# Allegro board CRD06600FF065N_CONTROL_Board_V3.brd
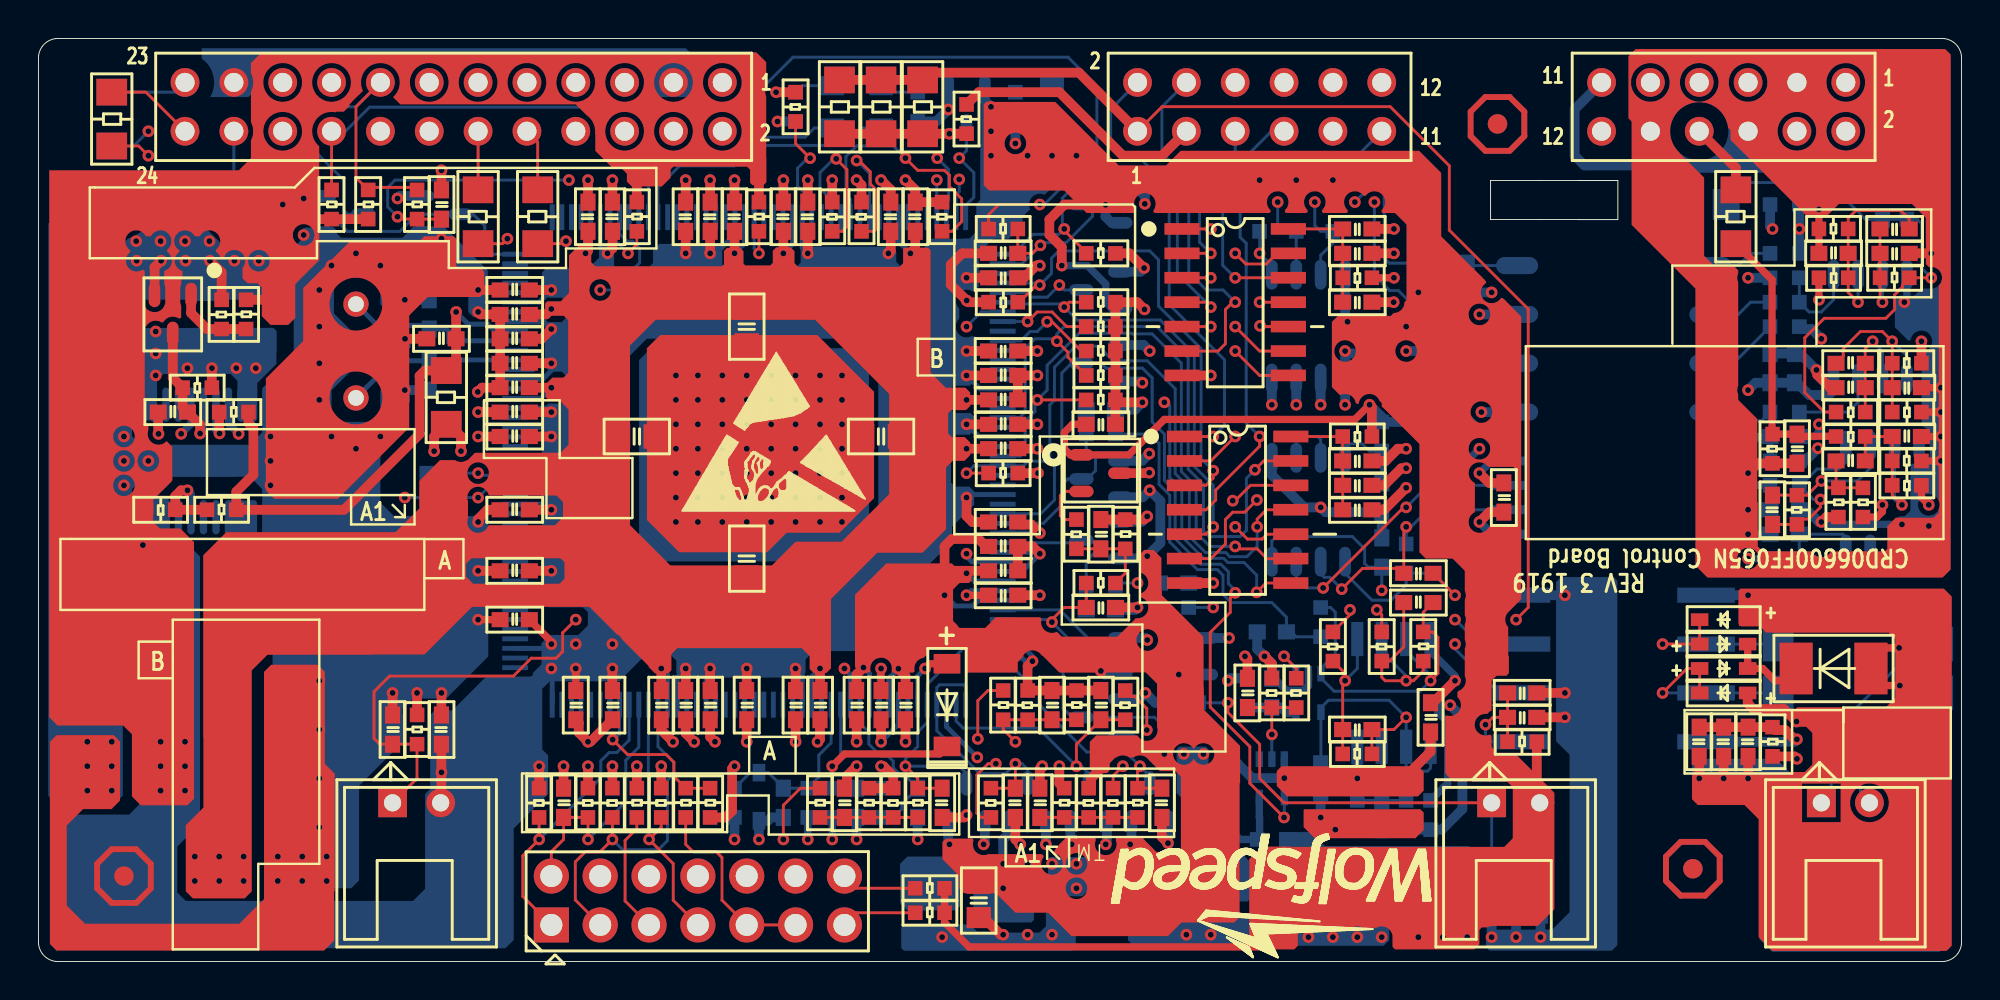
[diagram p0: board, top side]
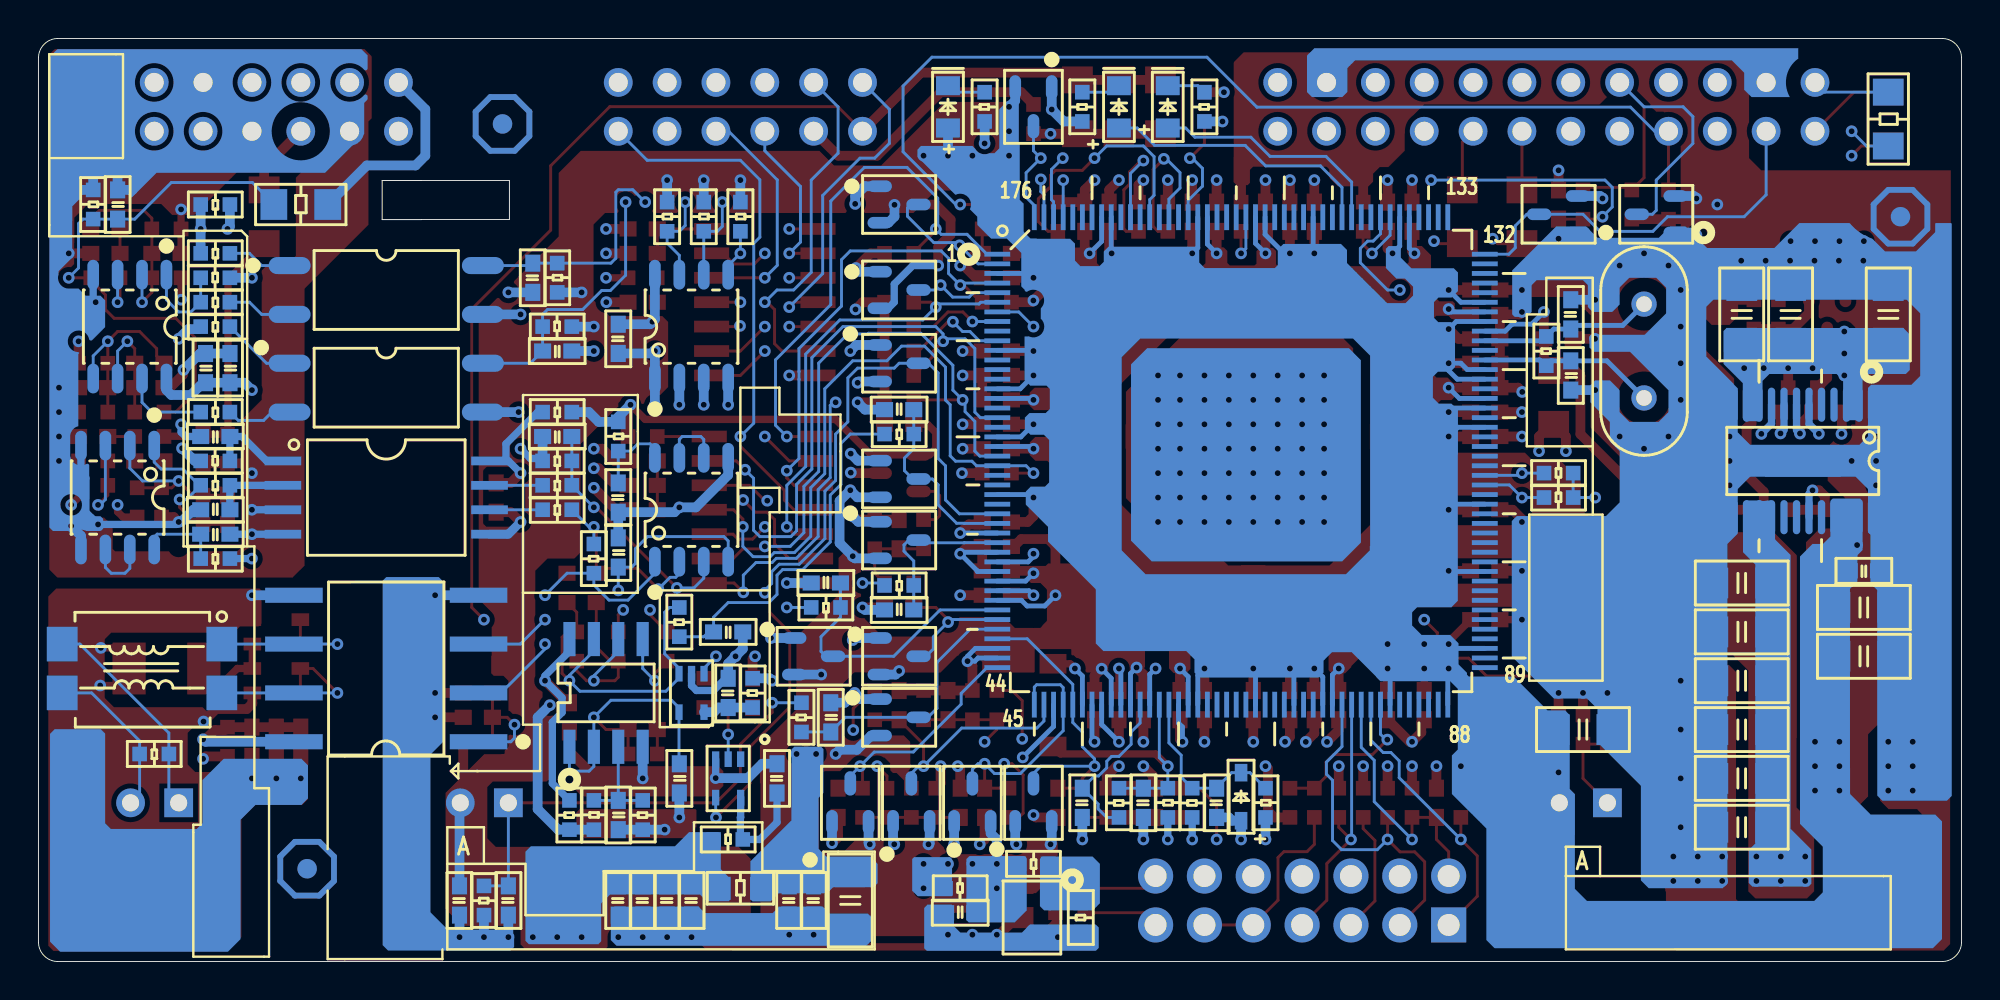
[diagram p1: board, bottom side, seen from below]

Outline 100 x 48.01 mm; copper layers: TOP, ART02, ART03, BOTTOM. Coordinates in mm from the lower left corner of the outline.
Outline path: 0,46.99 arc(0.3,47.71) 1.02,48.01 98.98,48.01 arc(99.7,47.71) 100,46.99 100,1.02 arc(99.7,0.3) 98.98,0 1.02,0 arc(0.3,0.3) 0,1.02 0,46.99 ; 75.51,40.62 80.08,40.62 80.08,40.62 82.13,40.62 82.13,38.59 80.08,38.59 80.08,38.59 75.51,38.59 75.51,40.62

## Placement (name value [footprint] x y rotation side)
C237  22n  [C0603]  91.44 26.67 90 top
C254  0.022n  [C0603]  20.32 30.48 90 bottom
C262  330p  [C0603]  68.58 12.06 0 top
C263  0.1u  [C0603]  64.14 13.97 270 bottom
C264  1n  [C0603]  62.87 13.97 90 top
C265  0.1u  [C0603]  61.59 9.53 270 bottom
C266  0.1u  [C0603]  72.39 12.7 90 top
C267  0.47u  [C0603]  69.85 7.62 90 bottom
C268  0.47u  [C0603]  66.67 9.53 90 bottom
C371  0.022n  [C0603]  20.32 33.66 270 bottom
C378  0.1u  [C0603]  27.3 8.26 90 top
C392  0.12n  [C0603]  50.16 36.83 180 top
C393  2.2n  [C0603]  50.8 8.26 270 top
C394  3.3n  [C0603]  58.42 8.26 270 top
C395  DNP  [C0603]  52.07 8.26 90 top
C396  0.1u  [C0603]  69.85 32.38 270 bottom
C397  680p  [C0603]  52.07 2.54 0 bottom
C398  0.1u  [C0603]  69.85 3.17 270 bottom
C399  0.1u  [C0603]  68.58 3.17 270 bottom
C400  0.1u  [C0603]  67.31 3.17 270 bottom
C401  0.1u  [C0603]  66.04 3.17 270 bottom
C402  0.1u  [C0603]  60.96 3.17 270 bottom
C403  0.1u  [C0603]  59.69 3.17 270 bottom
C404  4.7u  [C1206]  57.78 3.17 270 bottom
C405  1u  [C0603]  78.11 3.17 270 bottom
C406  1u  [C0603]  20.95 12.06 270 top
C407  0.47u  [C0603]  75.56 3.17 270 bottom
C408  0.47u  [C0603]  58.8 12.7 90 bottom
C409  0.47u  [C0603]  18.41 12.06 90 top
C410  0.47u  [C0603]  59.05 19.68 0 bottom
C445  0.1u  [C0603]  90.81 27.3 180 bottom
C446  2.2n  [C0603]  90.81 23.5 0 bottom
C447  0.1u  [C0603]  76.2 24.13 90 top
C448  0.33n  [C0603]  73.03 27.3 180 bottom
C449  0.33n  [C0603]  71.75 20.19 0 top
C450  0.47u  [C0603]  69.85 21.27 90 bottom
C451  0.47u  [C0603]  69.85 24.13 270 bottom
C452  4.7n  [C0603]  55.24 13.34 90 top
C453  0.15n  [C0603]  97.16 27.3 180 top
C454  0.15n  [C0603]  94.23 26.04 180 top
C455  0.15n  [C0603]  90.17 23.5 270 top
C457  0.47u  [C0603]  90.81 22.23 180 bottom
C458  0.47n  [C0603]  96.52 36.83 0 top
C459  0.1u  [C0603]  93.34 36.83 180 top
C460  0.15n  [C0603]  96.52 38.1 0 top
C462  0.47u  [C0603]  90.04 30.86 90 bottom
C463  0.12n  [C0603]  74.3 35.56 270 bottom
C464  0.12n  [C0603]  73.03 31.75 180 bottom
C465  0.47n  [C0603]  94.23 29.84 180 top
C466  0.15n  [C0603]  94.23 31.11 180 top
C467  0.12n  [C0603]  97.16 29.84 0 top
C471  1u  [C0603]  77.15 13.97 0 top
C472  0.1u  [C0603]  77.15 12.7 0 top
C473  1u  [C0603]  86.36 11.43 270 top
C474  0.1u  [C0603]  88.9 11.43 270 top
C475  0.01u  [C0603]  87.63 11.43 270 top
C483  2.2n  [C0603]  64.14 17.14 180 bottom
C484  4.7n  [C0603]  55.24 28.7 0 bottom
C488  2.2n  [C0603]  52.7 13.34 90 top
C489  4.7n  [C0603]  55.24 18.29 0 bottom
C490  1n  [C0603]  41.91 8.26 90 top
C491  3.3n  [C0603]  46.99 8.26 270 top
C492  0.01u  [C0603]  55.24 22.23 90 top
C493  0.01u  [C0603]  55.24 18.41 0 top
C494  0.1u  [C0603]  55.24 27.94 0 top
C495  330p  [C0603]  71.75 18.67 180 top
C496  10u  [C1206]  11.43 33.66 90 bottom
C497  10u  [C1206]  8.89 33.66 90 bottom
C499  0.1u  [C0603]  5.08 20.32 180 bottom
C500  10u  [C1206]  5.08 18.41 180 bottom
C501  10u  [C1206]  5.08 15.88 180 bottom
C504  10u  [C1206]  3.81 33.66 90 bottom
C505  0.1u  [C0603]  6.99 28.57 180 top
C506  10u  [C1206]  19.68 12.06 180 bottom
C507  10u  [C1206]  11.43 14.61 0 bottom
C508  10u  [C1206]  11.43 12.06 0 bottom
C509  10u  [C1206]  11.43 17.14 0 bottom
C510  10u  [C1206]  11.43 9.53 0 bottom
C511  10u  [C1206]  11.43 6.99 0 bottom
C512  2.2u  [C0805]  36.83 33.02 270 top
C513  2.2u  [C0805]  43.81 27.3 180 top
C514  2.2u  [C0805]  36.83 20.95 90 top
C515  2.2u  [C0805]  31.11 27.3 0 top
C516  10u  [C1206]  11.43 19.68 0 bottom
C518  0.1u  [C0603]  38.73 8.26 270 bottom
C519  22n  [C0603]  20.95 32.38 180 top
C520  0.1u  [C0603]  50.16 35.56 0 top
C521  2.2u  [C0603]  50.16 19.05 0 top
C522  2.2u  [C0603]  45.59 38.73 270 top
C523  2.2u  [C0603]  44.32 38.73 270 top
C524  2.2u  [C0603]  40.01 38.73 270 top
C525  2.2u  [C0603]  38.73 38.73 270 top
C526  2.2u  [C0603]  36.2 38.73 270 top
C527  2.2u  [C0603]  34.92 38.73 270 top
C528  2.2u  [C0603]  33.66 38.73 270 top
C529  2.2u  [C0603]  29.84 38.73 270 top
C530  2.2u  [C0603]  28.57 38.73 270 top
C531  2.2u  [C0603]  24.77 34.92 180 top
C532  2.2u  [C0603]  24.77 33.66 180 top
C533  2.2u  [C0603]  24.77 32.38 180 top
C534  2.2u  [C0603]  24.77 31.11 180 top
C535  2.2u  [C0603]  24.77 29.84 180 top
C536  2.2u  [C0603]  24.77 28.57 180 top
C537  2.2u  [C0603]  24.77 27.3 180 top
C538  2.2u  [C0603]  24.77 23.5 180 top
C539  2.2u  [C0603]  24.77 20.32 180 top
C540  2.2u  [C0603]  24.77 17.78 180 top
C541  2.2u  [C0603]  27.94 13.34 90 top
C542  2.2u  [C0603]  29.84 13.34 90 top
C543  2.2u  [C0603]  32.38 13.34 90 top
C544  2.2u  [C0603]  33.66 13.34 90 top
C545  2.2u  [C0603]  34.92 13.34 90 top
C546  2.2u  [C0603]  36.83 13.34 90 top
C547  2.2u  [C0603]  39.37 13.34 90 top
C548  2.2u  [C0603]  40.64 13.34 90 top
C549  2.2u  [C0603]  45.09 13.34 90 top
C550  2.2u  [C0603]  43.81 13.34 90 top
C551  2.2u  [C0603]  42.55 13.34 90 top
C552  0.1u  [C0603]  50.16 31.75 0 top
C553  0.1u  [C0603]  50.16 30.48 180 top
C554  2.2u  [C0603]  50.16 29.21 180 top
C555  0.1u  [C0603]  50.16 27.94 180 top
C556  2.2u  [C0603]  50.16 26.67 180 top
C557  0.1u  [C0603]  50.16 22.86 180 top
C558  2.2u  [C0603]  50.16 21.59 180 top
C559  2.2u  [C0603]  50.16 20.32 180 top
C560  0.1u  [C0603]  68.58 38.1 0 top
C561  0.01u  [C0603]  68.58 34.29 0 top
C562  1u  [C0603]  68.58 36.83 0 top
C563  0.1u  [C0603]  68.58 26.04 0 top
C564  0.01u  [C0603]  68.58 23.5 0 top
C565  1u  [C0603]  68.58 24.77 0 top
C566  0.47u  [C0603]  91.31 30.86 90 bottom
C592  2.2u  [C0805]  48.9 3.17 270 top
C593  1n  [C0603]  42.55 8.26 270 bottom
C594  0.47n  [C0603]  95.89 39.37 90 bottom
C595  1u  [C0603]  45.72 8.26 270 bottom
C596  0.12n  [C0603]  20.95 39.37 90 top
D48  2.2V  [SOD-123]  47.24 13.34 270 top
D84  BAV99  [SOT-23]  59.69 15.88 270 bottom
D85  BAV99  [SOT-23]  55.24 15.88 270 bottom
D86  BAV99  [SOT-23]  55.24 31.11 270 bottom
D87  BAV99  [SOT-23]  57.78 8.26 180 bottom
D88  BAV99  [SOT-23]  55.24 25.1 270 bottom
D89  BAV99  [SOT-23]  54.61 8.26 180 bottom
D90  BAV99  [SOT-23]  51.44 8.26 180 bottom
D91  BAV99  [SOT-23]  48.26 8.26 180 bottom
D92  BAV99  [SOT-23]  55.24 12.7 270 bottom
D93  BAV99  [SOT-23]  55.24 21.92 270 bottom
D94  BAV99  [SOT-23]  55.24 34.92 270 bottom
D95  BAV99  [SOT-23]  55.24 39.37 270 bottom
D96  BAV99  [SOT-23]  15.88 38.86 90 bottom
D97  BAV99  [SOT-23]  20.95 38.86 90 bottom
D98  BAV99  [SOT-23]  48.26 44.45 0 bottom
D102  RC-CL-170R-0805  [LED0805]  41.27 44.45 90 bottom
D103  RC-CL-170R-0805  [LED0805]  43.81 44.45 90 bottom
D104  RC-CL-170R-0805  [LED0805]  52.7 44.45 90 bottom
D110  BAS21WS-TP  [SOD-323]  87.63 13.97 180 top
D111  SMBJ15CA  [SMB]  93.34 15.24 180 top
D112  BAS21WS-TP  [SOD-323]  87.63 15.24 0 top
D113  BAS21WS-TP  [SOD-323]  87.63 17.78 180 top
D114  BAS21WS-TP  [SOD-323]  87.63 16.51 0 top
J2  PIN2*12-2.54-F  [CON_2MM54_12X2]  21.59 44.45 180 top
J3  PIN2*6-2.54-F  [CON_2MM54_6X2]  63.5 44.45 0 top
J4  PIN2*6-2.54-F  [CON_2MM54_6X2]  87.63 44.45 180 top
J5  2*7P 2.54  [CON_2MM54_7X2]  34.29 3.17 180 top
J11  XHB2.54-2P-F  [CON_2MM54_2X1]  92.71 8.26 180 top
J17  1*2P  [CONNECT_2MM54_2X1]  75.56 8.26 180 top
J18  1*2P  [CONNECT_2MM54_2X1]  18.41 8.26 180 top
L21  33uH 0.2A  [R0805]  63.5 3.81 0 bottom
NOREF  -  []  280.71 1.57 0 top
NOREF#2  -  []  38.34 26.64 0 top
NOREF#3  #VAL  [unnamed#2]  86.03 4.83 0 top
NOREF#4  -  []  0.39 -5 90 top
NOREF#5  -  []  0.01 -3.22 0 top
NOREF#6  -  []  0.01 -5.17 0 top
NOREF#7  -  []  187.11 64.82 0 top
NOREF#8  -  []  0.54 0 90 top
NOREF#9  #VAL  [unnamed#2]  75.87 43.56 0 top
NOREF#10  #VAL  [unnamed#2]  4.45 4.45 0 top
NOREF#11  #VAL  [unnamed#2]  3.17 38.73 180 bottom
NOREF#12  #VAL  [unnamed#2]  86.03 4.83 180 bottom
NOREF#13  #VAL  [unnamed#2]  75.87 43.56 180 bottom
Q1  2N7002/SOT  [SOT-23]  6.99 33.66 180 top
R16  1M  [R1206]  25.96 38.73 270 top
R49  470K  [R1206]  3.81 43.81 90 bottom
R58  24K  [R0603]  51.44 13.34 270 top
R133  12K  [R0603]  90.17 26.67 270 top
R221  1M  [R0603]  21.59 31.75 270 bottom
R224  3.9k  [R0603]  68.58 7.62 270 bottom
R225  3.9k  [R0603]  71.12 7.62 90 bottom
R226  13.3k  [R0603]  68.58 10.79 180 top
R229  10K  [R0603]  65.41 13.97 270 top
R230  DNP  [R0603]  64.14 13.97 270 top
R327  1R  [R0603]  31.11 38.73 90 top
R400  1R  [R0603]  37.47 38.73 90 top
R404  10k  [R0603]  26.04 8.26 270 top
R405  10k  [R0603]  29.84 8.26 270 top
R406  10k  [R0603]  32.38 8.26 270 top
R407  10k  [R0603]  34.92 8.26 90 top
R408  0  [R0603]  33.66 8.26 90 top
R409  0  [R0603]  31.11 8.26 90 top
R410  470  [R0603]  28.57 8.26 270 top
R411  2.2k  [R0603]  46.35 3.81 180 top
R412  2.2k  [R0603]  46.35 2.54 180 top
R414  2k  [R0603]  55.24 33.02 180 top
R415  2k  [R0603]  55.24 31.75 180 top
R416  2k  [R0603]  55.24 29.21 180 top
R417  2k  [R0603]  50.16 25.4 180 top
R418  2k  [R0603]  41.27 38.73 270 top
R419  2k  [R0603]  39.37 44.45 270 top
R420  2k  [R0603]  46.99 38.73 270 top
R421  2k  [R0603]  42.8 38.73 270 top
R422  2k  [R0603]  55.24 30.48 180 top
R423  2k  [R0603]  55.24 36.83 180 top
R424  2k  [R0603]  50.16 34.29 0 top
R425  2k  [R0603]  55.24 34.29 180 top
R431  1k  [R0603]  50.16 38.1 180 top
R432  1k  [R0603]  49.53 8.26 270 top
R433  DNP  [R0603]  54.61 8.26 270 top
R434  DNP  [R0603]  53.34 8.26 90 top
R435  0  [R0603]  55.88 8.26 270 top
R436  1k  [R0603]  57.15 8.26 90 top
R437  10k  [R0603]  63.5 38.73 90 bottom
R438  10k  [R0603]  65.41 38.73 90 bottom
R439  10k  [R0603]  67.31 38.73 90 bottom
R440  200  [R0603]  52.07 3.81 0 bottom
R441  1k  [R0603]  48.26 5.08 180 bottom
R442  3.57k  [R0603]  45.8 2.29 270 bottom
R443  2k  [R0603]  39.37 44.45 270 bottom
R444  2k  [R0603]  45.72 44.45 270 bottom
R445  2k  [R0603]  50.8 44.45 270 bottom
R446  2k  [R0603]  76.83 3.17 270 bottom
R447  3.3k  [R0603]  60.33 12.7 270 bottom
R448  2k  [R0603]  19.68 12.06 90 top
R449  3.3k  [R0603]  59.05 18.41 180 bottom
R482  2k  [R0603]  90.81 24.77 180 bottom
R483  10k  [R0603]  73.03 24.77 180 bottom
R484  10k  [R0603]  73.03 26.04 180 bottom
R485  10k  [R0603]  73.03 23.5 180 bottom
R486  10k  [R0603]  71.12 20.95 270 bottom
R487  2k  [R0603]  56.52 13.34 270 top
R488  150k  [R0603]  94.23 27.3 0 top
R489  100k  [R0603]  97.16 26.04 180 top
R491  100k  [R0603]  91.44 23.5 270 top
R492  1M  [R0603]  97.16 24.77 0 top
R493  1M  [R0603]  94.87 23.88 90 top
R494  150k  [R0603]  93.6 23.88 90 top
R495  2k  [R0603]  96.52 35.56 180 top
R496  2k  [R0603]  93.34 35.56 0 top
R497  3k  [R0603]  93.34 38.1 180 top
R499  2k  [R0603]  90.81 34.29 180 bottom
R500  3K  [R0603]  90.81 36.83 180 bottom
R502  3.9k  [R0603]  73.03 35.56 90 bottom
R503  3K  [R0603]  90.81 33.02 180 bottom
R505  3.9k  [R0603]  73.03 33.02 0 bottom
R506  1k  [R0603]  94.23 28.57 0 top
R507  47k  [R0603]  97.16 31.11 180 top
R508  1.1k  [R0603]  97.16 28.57 0 top
R510  1k  [R0603]  90.81 28.57 180 bottom
R514  620  [R0603]  20.95 24.13 0 bottom
R515  10k  [R0603]  20.95 25.4 0 bottom
R516  0  [R0603]  90.17 11.43 90 top
R517  120  [R0603]  93.98 10.79 180 bottom
R524  1k  [R0603]  66.67 17.65 270 bottom
R525  1k  [R0603]  55.24 27.43 180 bottom
R528  24k  [R0603]  53.98 13.34 90 top
R529  1k  [R0603]  55.24 19.56 180 bottom
R530  24k  [R0603]  43.18 8.26 90 top
R531  1k  [R0603]  45.72 8.26 90 top
R532  100  [R0603]  53.98 22.23 270 top
R533  470k  [R0603]  56.52 22.23 90 top
R534  3.3k  [R0603]  55.24 19.68 180 top
R535  13.3k  [R0603]  72.01 16.38 90 top
R536  10k  [R0603]  8.26 29.84 0 top
R537  1.5k  [R0603]  10.79 33.66 90 top
R538  12k  [R0603]  9.53 33.66 270 top
R540  100k  [R0603]  6.35 23.5 0 top
R541  0R  [R0603]  9.53 23.5 180 top
R544  2.2k  [R0603]  40.01 8.26 270 bottom
R545  2.2k  [R0603]  36.2 8.26 90 bottom
R546  10k  [R1206]  21.21 29.34 270 top
R547  0  [R0603]  10.16 28.57 180 top
R549  2.2R  [R0603]  68.58 35.56 0 top
R550  2.2R  [R0603]  68.58 27.3 0 top
R569  10k  [R0603]  90.81 35.56 0 bottom
R572  1M  [R1206]  22.86 38.73 270 top
R573  620k  [R1206]  88.27 38.73 270 top
R574  620k  [R1206]  86.36 39.37 0 bottom
R575  12K  [R0603]  97.16 39.37 90 bottom
R578  24K  [R0603]  44.45 8.26 270 top
R579  470K  [R1206]  3.81 43.81 90 top
R580  20R  [R1206]  45.97 44.45 90 top
R581  20R  [R1206]  43.81 44.45 90 top
R582  20R  [R1206]  41.66 44.45 90 top
R583  1k  [R0603]  41.27 8.26 90 bottom
R588  0  [R0603]  48.26 43.81 270 top
R589  10R  [R0603]  72.39 7.62 270 bottom
R590  10R  [R0603]  62.87 13.97 270 bottom
R591  10R  [R0603]  64.14 6.35 0 bottom
R592  10R  [R0603]  90.81 20.95 180 bottom
R593  10R  [R0603]  90.81 26.04 0 bottom
R594  10R  [R0603]  73.03 28.57 180 bottom
R595  10R  [R0603]  69.85 27.3 90 bottom
R597  10R  [R0603]  90.81 39.37 180 bottom
R598  10R  [R0603]  77.15 11.43 180 top
R599  10k  [R0603]  43.81 8.26 270 bottom
R600  10K  [R0603]  50.16 13.34 90 top
R601  10K  [R0603]  40.64 8.26 90 top
R602  10k  [R0603]  69.85 16.38 270 top
R603  10k  [R0603]  67.31 16.38 270 top
R604  10k  [R0603]  15.24 39.37 90 top
R605  1k  [R0603]  19.68 39.37 90 top
R606  10k  [R0603]  17.14 39.37 90 top
T1  TRNSFMR TV105  [ZJYS81]  94.61 15.24 0 bottom
U9  AZ431  [SOT23_1-32]  48.34 2.29 0 bottom
U28  TMS320F28377D  [LQFP176-050-2424]  37.47 26.04 270 bottom
U32  24C16BT-I/SN  [SOIC-8]  66.04 33.02 90 bottom
U36  SN74LVC1G17  [DCK]  64.14 9.53 0 bottom
U37  TLV3201  [SOT23-5]  66.04 13.97 0 bottom
U43  ACPL-C870-500E  [SSO-8]  81.92 24.13 270 bottom
U44  OPA2376  [SOIC-8]  95.89 24.13 270 bottom
U45  OPA2376  [SOIC-8]  66.04 23.5 90 bottom
U48  LM2903  [SOIC-8]  95.25 33.02 270 bottom
U53  1050  [SO-G8]  81.92 15.24 0 bottom
U55  LM50CIM3  [SOT-23]  55.24 25.4 270 top
U56  OPA2376AIDR  [WCSP-8]  70.48 13.97 90 bottom
U57  TPS70445PWP_TSSOP24  [TSSOP24]  8.26 26.04 270 bottom
U58  MC74VHCT50A_SOIC14  [SOIC14]  62.23 34.29 0 top
U59  MC74VHCT50A_SOIC14  [SOIC14]  62.35 23.5 0 top
U60  -  [TCLT1003]  81.92 34.92 180 bottom
U61  -  [TCLT1003]  81.92 29.84 180 bottom
Y1  HLX32 20MHz  [TSX-3225]  16.51 31.75 270 bottom
ZD3  2.5V  [SOD-323]  37.47 8.57 90 bottom

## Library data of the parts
C237 C254 C262-C268 C371 C378 C392-C403 C405-C410 C445-C455 C457-C460 C462-C467 C471-C475 C483 C484 C488-C495 C499 C505 C518-C566 C593-C596 = C0603: Tolerance: #TOL; User Part Number: HAMP
C404 C496 C497 C500 C501 C504 C506-C511 C516 = C1206: Tolerance: #TOL; User Part Number: HAMP
C512-C515 C592 = C0805: Tolerance: #TOL; User Part Number: HAMP
D48 = SOD-123: User Part Number: HAMP; Tolerance: #TOL
D84-D98 Q1 U55 = SOT-23: Tolerance: #TOL; User Part Number: HAMP
D102-D104 = LED0805: Tolerance: #TOL; User Part Number: HAMP
D110 D112-D114 ZD3 = SOD-323: Tolerance: #TOL; User Part Number: HAMP
D111 = SMB: Tolerance: #TOL; User Part Number: HAMP
J2 = CON_2MM54_12X2: Tolerance: #TOL; User Part Number: HAMP
J3 J4 = CON_2MM54_6X2: Tolerance: #TOL; User Part Number: HAMP
J5 = CON_2MM54_7X2: Tolerance: #TOL; User Part Number: HAMP
J11 = CON_2MM54_2X1: Tolerance: #TOL; User Part Number: HAMP
J17 J18 = CONNECT_2MM54_2X1: Tolerance: #TOL; User Part Number: HAMP
L21 = R0805: Tolerance: #TOL; User Part Number: HAMP
NOREF#3 NOREF#9-NOREF#13 = -: Tolerance: #TOL; User Part Number: HAMP
R16 R49 R546 R572-R574 R579-R582 = R1206: Tolerance: #TOL; User Part Number: HAMP
R58 R133 R221 R224-R226 R229 R230 R327 R400 R404-R412 R414-R425 R431-R449 R482-R489 R491-R497 R499 R500 R502 R503 R505-R508 R510 R514-R517 R524 R525 R528-R538 R540 R541 R544 R545 R547 R549 R550 R569 R575 R578 R583 R588-R595 R597-R606 = R0603: Tolerance: #TOL; User Part Number: HAMP
T1 = ZJYS81: Tolerance: #TOL; User Part Number: HAMP
U9 = SOT23_1-32: Tolerance: #TOL; User Part Number: HAMP
U28 = LQFP176-050-2424: Tolerance: #TOL; User Part Number: HAMP
U32 U44 U45 U48 = SOIC-8: Tolerance: #TOL; User Part Number: HAMP
U36 = DCK: Tolerance: #TOL; User Part Number: HAMP
U37 = SOT23-5: Tolerance: #TOL; User Part Number: HAMP
U43 = SSO-8: Tolerance: #TOL; User Part Number: HAMP
U53 = SO-G8: Tolerance: #TOL; User Part Number: HAMP
U56 = WCSP-8: Tolerance: #TOL; User Part Number: HAMP
U57 = TSSOP24: Tolerance: #TOL; User Part Number: HAMP
U58 U59 = SOIC14: Tolerance: #TOL; User Part Number: HAMP
U60 U61 = TCLT1003: Tolerance: #TOL; User Part Number: HAMP
Y1 = TSX-3225: Tolerance: #TOL; User Part Number: HAMP

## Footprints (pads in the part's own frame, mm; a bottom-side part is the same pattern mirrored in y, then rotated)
C0603
  rect 0.889x0.787 smd: 1(-0.76,0) 2(0.76,0)
C0805
  rect 1.092x1.27 smd: 1(-0.89,0) 2(0.89,0)
C1206
  rect 1.397x1.6 smd: 1(-1.4,0) 2(1.4,0)
CON_2MM54_2X1
  rect 1.499x1.499 hole 0.889: 1(0,0)
  round 1.499 hole 0.889: 2(-2.5,0)
CON_2MM54_6X2
  round 1.499 hole 0.991: 1(-6.35,-1.27) 2(-6.35,1.27) 3(-3.81,-1.27) 4(-3.81,1.27) 5(-1.27,-1.27) 6(-1.27,1.27) 7(1.27,-1.27) 8(1.27,1.27) 9(3.81,-1.27) 10(3.81,1.27) 11(6.35,-1.27) 12(6.35,1.27)
CON_2MM54_7X2
  rect 1.829x1.829 hole 1.143: 1(7.62,1.271)
  round 1.829 hole 1.143: 2(7.62,-1.271) 3(5.08,1.271) 4(5.08,-1.271) 5(2.54,1.271) 6(2.54,-1.271) 7(0,1.271) 8(0,-1.271) 9(-2.54,1.271) 10(-2.54,-1.271) 11(-5.08,1.271) 12(-5.08,-1.271) 13(-7.62,1.271) 14(-7.62,-1.271)
CON_2MM54_12X2
  round 1.499 hole 0.991: 1(-13.97,-1.27) 2(-13.97,1.27) 3(-11.43,-1.27) 4(-11.43,1.27) 5(-8.89,-1.27) 6(-8.89,1.27) 7(-6.35,-1.27) 8(-6.35,1.27) 9(-3.81,-1.27) 10(-3.81,1.27) 11(-1.27,-1.27) 12(-1.27,1.27) 13(1.27,-1.27) 14(1.27,1.27) 15(3.81,-1.27) 16(3.81,1.27) 17(6.35,-1.27) 18(6.35,1.27) 19(8.89,-1.27) 20(8.89,1.27) 21(11.43,-1.27) 22(11.43,1.27) 23(13.97,-1.27) 24(13.97,1.27)
CONNECT_2MM54_2X1
  rect 1.499x1.499 hole 0.889: 1(0,0)
  round 1.499 hole 0.889: 2(-2.5,0)
DCK
  rect 0.381x0.813 smd: 1(-0.65,-1) 2(0,-1) 3(0.65,-1) 4(0.65,1) 5(-0.65,1)
LED0805
  rect 0.991x1.245 smd: 1(1.1,0) 2(-1.1,0)
LQFP176-050-2424
  rect 8.636x8.636 smd: 0(0,0)
  rect 0.254x1.346 smd: 1(-10.75,-12.675) 2(-10.25,-12.675) 3(-9.75,-12.675) 4(-9.25,-12.675) 5(-8.75,-12.675) 6(-8.25,-12.675) 7(-7.75,-12.675) 8(-7.25,-12.675) 9(-6.75,-12.675) 10(-6.25,-12.675) 11(-5.75,-12.675) 12(-5.25,-12.675) 13(-4.75,-12.675) 14(-4.25,-12.675) 15(-3.75,-12.675) 16(-3.25,-12.675) 17(-2.75,-12.675) 18(-2.25,-12.675) 19(-1.75,-12.675) 20(-1.25,-12.675) 21(-0.75,-12.675) 22(-0.25,-12.675) 23(0.25,-12.675) 24(0.75,-12.675) 25(1.25,-12.675) 26(1.75,-12.675) 27(2.25,-12.675) 28(2.75,-12.675) 29(3.25,-12.675) 30(3.75,-12.675) 31(4.25,-12.675) 32(4.75,-12.675) 33(5.25,-12.675) 34(5.75,-12.675) 35(6.25,-12.675) 36(6.75,-12.675) 37(7.25,-12.675) 38(7.75,-12.675) 39(8.25,-12.675) 40(8.75,-12.675) 41(9.25,-12.675) 42(9.75,-12.675) 43(10.25,-12.675) 44(10.75,-12.675) 89(10.75,12.675) 90(10.25,12.675) 91(9.75,12.675) 92(9.25,12.675) 93(8.75,12.675) 94(8.25,12.675) 95(7.75,12.675) 96(7.25,12.675) 97(6.75,12.675) 98(6.25,12.675) 99(5.75,12.675) 100(5.25,12.675) 101(4.75,12.675) 102(4.25,12.675) 103(3.75,12.675) 104(3.25,12.675) 105(2.75,12.675) 106(2.25,12.675) 107(1.75,12.675) 108(1.25,12.675) 109(0.75,12.675) 110(0.25,12.675) 111(-0.25,12.675) 112(-0.75,12.675) 113(-1.25,12.675) 114(-1.75,12.675) 115(-2.25,12.675) 116(-2.75,12.675) 117(-3.25,12.675) 118(-3.75,12.675) 119(-4.25,12.675) 120(-4.75,12.675) 121(-5.25,12.675) 122(-5.75,12.675) 123(-6.25,12.675) 124(-6.75,12.675) 125(-7.25,12.675) 126(-7.75,12.675) 127(-8.25,12.675) 128(-8.75,12.675) 129(-9.25,12.675) 130(-9.75,12.675) 131(-10.25,12.675) 132(-10.75,12.675)
  rect 1.346x0.254 smd: 45(12.675,-10.75) 46(12.675,-10.25) 47(12.675,-9.75) 48(12.675,-9.25) 49(12.675,-8.75) 50(12.675,-8.25) 51(12.675,-7.75) 52(12.675,-7.25) 53(12.675,-6.75) 54(12.675,-6.25) 55(12.675,-5.75) 56(12.675,-5.25) 57(12.675,-4.75) 58(12.675,-4.25) 59(12.675,-3.75) 60(12.675,-3.25) 61(12.675,-2.75) 62(12.675,-2.25) 63(12.675,-1.75) 64(12.675,-1.25) 65(12.675,-0.75) 66(12.675,-0.25) 67(12.675,0.25) 68(12.675,0.75) 69(12.675,1.25) 70(12.675,1.75) 71(12.675,2.25) 72(12.675,2.75) 73(12.675,3.25) 74(12.675,3.75) 75(12.675,4.25) 76(12.675,4.75) 77(12.675,5.25) 78(12.675,5.75) 79(12.675,6.25) 80(12.675,6.75) 81(12.675,7.25) 82(12.675,7.75) 83(12.675,8.25) 84(12.675,8.75) 85(12.675,9.25) 86(12.675,9.75) 87(12.675,10.25) 88(12.675,10.75) 133(-12.675,10.75) 134(-12.675,10.25) 135(-12.675,9.75) 136(-12.675,9.25) 137(-12.675,8.75) 138(-12.675,8.25) 139(-12.675,7.75) 140(-12.675,7.25) 141(-12.675,6.75) 142(-12.675,6.25) 143(-12.675,5.75) 144(-12.675,5.25) 145(-12.675,4.75) 146(-12.675,4.25) 147(-12.675,3.75) 148(-12.675,3.25) 149(-12.675,2.75) 150(-12.675,2.25) 151(-12.675,1.75) 152(-12.675,1.25) 153(-12.675,0.75) 154(-12.675,0.25) 155(-12.675,-0.25) 156(-12.675,-0.75) 157(-12.675,-1.25) 158(-12.675,-1.75) 159(-12.675,-2.25) 160(-12.675,-2.75) 161(-12.675,-3.25) 162(-12.675,-3.75) 163(-12.675,-4.25) 164(-12.675,-4.75) 165(-12.675,-5.25) 166(-12.675,-5.75) 167(-12.675,-6.25) 168(-12.675,-6.75) 169(-12.675,-7.25) 170(-12.675,-7.75) 171(-12.675,-8.25) 172(-12.675,-8.75) 173(-12.675,-9.25) 174(-12.675,-9.75) 175(-12.675,-10.25) 176(-12.675,-10.75)
R0603
  rect 0.762x0.762 smd: 1(-0.76,0) 2(0.76,0)
R0805
  rect 0.991x1.194 smd: 1(-1,0) 2(1,0)
R1206
  rect 1.397x1.6 smd: 1(-1.4,0) 2(1.4,0)
SMB
  rect 1.727x2.692 smd: 1(-1.943,0) 2(1.943,0)
SO-G8
  rect 2.997x0.787 smd: 1(-4.8,3.81) 2(-4.8,1.27) 3(-4.8,-1.27) 4(-4.8,-3.81) 5(4.8,-3.81) 6(4.8,-1.27) 7(4.8,1.27) 8(4.8,3.81)
SOD-123
  rect 1.02x1.4 smd: 1(-2.15,0) 2(2.15,0)
SOD-323
  rect 0.914x0.66 smd: 1(-1.25,0) 2(1.25,0)
SOIC14
  rect 1.829x0.61 smd: 1(-2.765,3.81) 2(-2.765,2.54) 3(-2.765,1.27) 4(-2.765,0) 5(-2.765,-1.27) 6(-2.765,-2.54) 7(-2.765,-3.81) 8(2.765,-3.81) 9(2.765,-2.54) 10(2.765,-1.27) 11(2.765,0) 12(2.765,1.27) 13(2.765,2.54) 14(2.765,3.81)
SOIC-8
  oval 1.549x0.61 smd: 1(-2.7,1.905) 2(-2.7,0.635) 3(-2.7,-0.635) 4(-2.7,-1.905) 5(2.7,-1.905) 6(2.7,-0.635) 7(2.7,0.635) 8(2.7,1.905)
SOT23-5
  rect 0.381x0.813 smd: 1(-0.65,-1) 2(0,-1) 3(0.65,-1) 4(0.65,1) 5(-0.65,1)
SOT23_1-32
  oval 0.61x1.27 smd: 1(-0.95,-1.01) 2(0.95,-1.01) 3(0,1.01)
SOT-23
  oval 0.61x1.27 smd: 1(-0.95,-1.01) 2(0.95,-1.01) 3(0,1.01)
SSO-8
  rect 0.457x1.905 smd: 1(-1.905,-5.373) 2(-0.635,-5.373) 3(0.635,-5.373) 4(1.905,-5.373) 5(1.905,5.373) 6(0.635,5.373) 7(-0.635,5.373) 8(-1.905,5.373)
TCLT1003
  oval 2.184x0.889 smd: 1(-5.025,1.27) 2(-5.025,-1.27) 3(5.025,-1.27) 4(5.025,1.27)
TSSOP24
  oval 1.778x0.381 smd: 1(-2.925,3.575) 2(-2.925,2.925) 3(-2.925,2.275) 4(-2.925,1.625) 5(-2.925,0.975) 6(-2.925,0.325) 7(-2.925,-0.325) 8(-2.925,-0.975) 9(-2.925,-1.625) 10(-2.925,-2.275) 11(-2.925,-2.925) 12(-2.925,-3.575) 13(2.925,-3.575) 14(2.925,-2.925) 15(2.925,-2.275) 16(2.925,-1.625) 17(2.925,-0.975) 18(2.925,-0.325) 19(2.925,0.325) 20(2.925,0.975) 21(2.925,1.625) 22(2.925,2.275) 23(2.925,2.925) 24(2.925,3.575)
  rect 1.651x3.937 smd: 25(0,0)
TSX-3225
  round 1.321 hole 0.813: 1(-2.44,0) 2(2.44,0)
unnamed#2
  round 1.016 smd: 1(0,0)
WCSP-8
  rect 1.778x0.635 smd: 1(-2.8,1.905) 2(-2.8,0.635) 3(-2.8,-0.635) 4(-2.8,-1.905) 5(2.8,-1.905) 6(2.8,-0.635) 7(2.8,0.635) 8(2.8,1.905)
ZJYS81
  rect 1.6x1.803 smd: 1(-4.15,-1.27) 2(-4.15,1.27) 3(4.15,1.27) 4(4.15,-1.27)

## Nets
AGND: C254.1 C263.1 C264.2 C265.1 C266.1 C267.1 C268.1 C371.1 C378.2 C392.2 C393.2 C394.2 C395.2 C396.2 C397.2 C398.2 C399.2 C400.2 C401.2 C402.2 C403.2 C404.2 C405.2 C406.1 C407.2 C408.2 C409.2 C410.2 C447.1 C448.1 C450.2 C451.2 C452.2 C463.2 C464.2 C471.2 C472.2 C483.2 C484.2 C488.2 C489.2 C490.2 C491.2 C492.2 C493.2 C494.2 C496.2 C497.2 C499.2 C500.2 C501.2 C504.2 C505.2 C506.2 C507.2 C508.2 C509.2 C510.2 C511.2 C512.2 C513.2 C514.2 C515.2 C516.2 C518.2 C519.2 C520.2 C521.2 C522.1 C523.1 C524.1 C525.1 C526.1 C527.1 C528.1 C529.1 C530.1 C531.2 C532.2 C533.2 C534.2 C535.2 C536.2 C537.2 C538.2 C539.2 C540.2 C541.1 C542.1 C543.1 C544.1 C545.1 C546.1 C547.1 C548.1 C549.1 C550.1 C551.1 C552.2 C553.1 C554.1 C555.1 C556.1 C557.1 C558.1 C559.1 C560.2 C561.2 C562.2 C563.2 C564.2 C565.2 C592.2 C593.2 C595.2 C596.2 D48.1 D84.1 D85.1 D86.1 D87.1 D88.1 D89.1 D90.1 D91.1 D92.1 D93.1 D94.1 D95.1 D96.1 D97.1 D98.1 J2.2 J2.3 J2.4 J2.21 J3.6 J3.8 J5.4 J5.6 J5.8 J5.10 J5.12 Q1.2 R58.1 R224.2 R230.1 R410.1 R414.1 R415.1 R416.1 R417.1 R418.1 R419.1 R420.1 R421.1 R422.1 R423.1 R424.1 R425.1 R434.2 R442.2 R443.2 R444.2 R445.2 R446.2 R448.2 R484.1 R528.2 R530.2 R533.2 R538.1 R545.1 R578.1 R580.1 R581.1 R582.1 R588.2 U9.3 U28.0 U28.30 U28.32 U28.33 U28.34 U28.42 U28.43 U28.47 U28.50 U28.51 U28.52 U28.57 U28.60 U32.1 U32.2 U32.3 U32.4 U36.3 U37.2 U43.5 U45.5 U53.4 U55.3 U56.4 U57.1 U57.6 U57.9 U57.12 U57.13 U57.24 U57.25 U58.7 U59.7 U60.3 U61.3 ZD3.1
DGND: C237.1 C445.1 C446.2 C453.1 C457.2 C458.2 C459.2 C462.2 C465.2 C467.2 C566.2 C594.2 J4.3 J4.6 J4.10 R133.2 R489.1 R494.1 R497.2 R508.2 R575.2 U43.3 U43.4 U44.4 U44.5 U48.4
VDD: C507.1 C508.1 C509.1 C510.1 C511.1 C512.1 C513.1 C514.1 C515.1 C516.1 C522.2 C525.2 C526.2 C530.2 C532.1 C535.1 C543.2 C548.2 C554.2 C556.2 U28.16 U28.21 U28.61 U28.76 U28.117 U28.126 U28.137 U28.153 U28.158 U28.169 U57.14 U57.15 U57.16
/TRST_P: C378.1 J5.2 R410.2 U28.79
/WP_PFC: R439.1 U28.175 U32.7
_AD_DC_CUR: C393.1 D90.3 R432.1 U28.45 U28.48
_AD_DCTEMP: C408.1 D92.3 R447.2 U28.40
_AD_PFCTEMP: C410.1 D84.3 R449.2 U28.38
_AD_VAC: C484.1 D88.3 R525.2 U28.29
_AD_VPFC_CTRL: C489.1 D93.3 R529.2 U28.31
_AD_VPFC_PROTECT: C491.1 D91.3 R531.2 U28.41 U28.49
_DCOCP: C392.1 D95.3 R431.1 U28.2
_PFC_OCP: C596.1 R605.1 U28.7
_PFCCURBSAMP: C394.1 D87.3 R436.2 U28.44
AC_L_SAMP_D: J2.10 R16.1
AC_N_D: J2.12 R572.1
AD_AIR_TEMP: C493.1 D85.3 R534.2 U28.39
AD_DC_CUR: J2.16 R432.2
AD_DCVOLT1: C452.1 D89.3 R487.2 U28.46
CAN5V_GND: C473.2 C474.2 C475.2 D110.1 D111.1 D113.1 J4.2 U53.5
CAN_5V: J4.4 R516.1
CANRX: R514.2 U28.108 U53.2
CANTX: R515.2 U28.109 U28.140 U53.3
CS: J3.1 R580.2 R581.2 R582.2 R583.1
CS_ADC: C593.1 D48.2 R583.2 R599.1 U28.58
CS_RTN: J3.3 R588.1
DCOCP: J2.18 R431.2 R604.2
DCOVP: C463.1 D98.3 R502.2 U28.176 U60.4
DCPWM1A_1H: J3.4 U58.6
DCPWM1A_1HH: R419.2 U28.160 U58.5
DCPWM1A_1L: J3.2 U58.4
DCPWM1A_1LL: R418.2 U28.162 U58.3
DCPWM2A_2H: J3.7 U58.12
DCPWM2A_2HH: R420.2 U28.164 U58.13
DCPWM2A_2L: J3.5 U58.2
DCPWM2A_2LL: R421.2 U28.166 U58.1
DCSHORT: C464.1 D94.3 R505.2 U28.5 U61.4
DCVOLT1: C455.2 R482.1 R491.2 U44.1
P_ADREF3.2V: C397.1 C549.2 C551.2 C558.2 C559.2 C592.1 D84.2 D85.2 D86.2 D87.2 D88.2 D89.2 D90.2 D91.2 D92.2 D93.2 R433.1 R440.1 R441.1 U9.2 U28.35 U28.37 U28.53 U28.55
P_SCL: R438.1 U28.174 U32.6
P_SDA: R437.1 U28.173 U32.5
P_WD_GREEN: D102.2 U28.143
P_WD_RED: D103.2 U28.144
PFC-FB: J2.23 R49.2
PFC-VO: J2.24 R579.2
PFC_OCP: D96.3 J2.15 R605.2 R606.2
PFCCURBSAMP: J2.17 R435.1
PWM1A: J2.11 U58.8
PWM1AA: R414.2 U28.8 U58.9
PWM1B: J2.5 U58.10
PWM1BB: R415.2 U28.10 U58.11
PWM1C: J2.7 U59.8
PWM1CC: R416.2 U28.22 U59.9
PWM1D: J2.9 U59.10
PWM1DD: R417.2 U28.23 U59.11
REF1: C262.2 C268.2 R226.1 U37.4 U56.1 U56.2
RLYCTRL1: D97.3 J2.22 U28.132
SR-PWM-A: J3.9 U59.12
SR-PWM-AA: R422.2 U28.18 U59.13
SR-PWM-B: J3.10 U59.2
SR-PWM-BB: R423.2 U28.1 U59.1
SR-PWM-C: J3.11 U59.4
SR-PWM-CC: R424.2 U28.4 U59.3
SR-PWM-D: J3.12 U59.6
SR-PWM-DD: R425.2 U28.6 U59.5
TCK_P: R407.2 R408.2 U28.81
TDI_P: J5.3 R405.2 U28.77
TDO_P: J5.7 R406.2 U28.78
TMS_P: J5.1 R404.2 U28.80
VAC_POLARITY+: D86.3 U28.28 U36.4
VO1+: J4.11 R574.1
VO2+: J4.8 R573.1
VP3.3A: C402.1 C403.1 C404.1 C521.1 C550.2 L21.1 R225.1 R589.2 R590.1 U28.36 U28.54
VP3.3D: C396.1 C398.1 C399.1 C400.1 C401.1 C405.1 C406.2 C499.1 C500.1 C501.1 C506.1 C520.1 C523.2 C524.2 C527.2 C528.2 C529.2 C531.1 C533.1 C534.1 C536.1 C537.1 C538.1 C539.1 C540.1 C541.2 C542.2 C544.2 C545.2 C546.2 C547.2 C552.1 C553.2 C555.2 C557.2 D94.2 D95.2 D96.2 D97.2 D98.2 D104.2 J17.2 J18.2 L21.2 R327.2 R400.2 R404.1 R405.1 R406.1 R407.1 R409.2 R411.1 R412.1 R437.2 R438.2 R439.2 R502.1 R505.1 R537.2 R540.1 R546.2 R591.2 R598.1 R604.1 R606.1 U28.3 U28.11 U28.15 U28.20 U28.26 U28.62 U28.68 U28.72 U28.75 U28.82 U28.88 U28.91 U28.99 U28.106 U28.114 U28.116 U28.119 U28.120 U28.125 U28.127 U28.138 U28.147 U28.152 U28.159 U28.168 U32.8 U57.21 U57.22 U57.23
VP+5V: C494.1 C496.1 C497.1 C504.1 J2.20 R440.2 R536.2 R544.2 R549.2 R550.2 R594.2 R595.2 U55.1 U57.2 U57.3 U57.10 U57.11
VP+15V: J2.14
VP-5V: C450.1 J2.19 U45.4
VS+5V: J4.7 R492.2 R493.1 R496.1 R507.1 R592.2 R593.2
VS+15V: J4.1 R500.1 R503.1 R569.1 R597.1
VS+15V_U48: C462.1 C566.1 R597.2 U48.8
VS-5V: J4.5
X1: C371.2 R221.1 U28.123 Y1.1
X2: C254.2 R221.2 U28.121 Y1.2
XRS: C519.1 R541.1 R546.1 R547.1 U28.124
N16777869: J5.9 J5.11 R408.1
N16779815: R327.1 U28.139
N16809513: J5.5 R409.1
N16810933: J5.13 R412.2
N16810951: J5.14 R411.2
N16824215: C395.1 R433.2 R434.1 R435.2 R436.1
N16830570: R441.2 R442.1 U9.1
N16833081: D102.1 R443.1
N16833084: D103.1 R444.1
N16833087: D104.1 R445.1
N16835391: C407.1 J17.1 R446.1 R447.1
N16836592: C409.1 J18.1 R448.1 R449.1
N16848574: C446.1 R482.2 U43.2
N16848598: C445.2 R593.1 U43.1
N16848614: C447.2 R594.1 U43.8
N16848642: R483.1 U43.7
N16848644: C448.2 R483.2 R484.2 U45.3
N16848814: R485.1 U43.6
N16848816: C449.1 R485.2 R486.1 U45.2
N16848832: C449.2 R486.2 R487.1 U45.1
N16848970: U44.6 U44.7
N16848978: C453.2 C454.1 R488.2 R489.2 R492.1 U44.3
N16848994: C454.2 C455.1 R491.1 R493.2 R494.2 U44.2
N16849016: C457.1 R592.1 U44.8
N16851028: U45.6 U45.7
N16851046: C451.1 R595.1 U45.8
N16853569: C458.1 C460.1 R495.2 U48.3
N16853931: C459.1 C460.2 R496.2 R497.1 U48.2
N16853972: R499.1 R569.2 U48.1
N16854569: R500.2 U60.1
N16855013: C466.2 C467.1 R507.2 R508.1 U48.5
N16855828: C465.1 C466.1 R506.2 U48.6
N16855912: R510.2 U61.2
N16855916: R503.2 U61.1
N16860426: C471.1 C472.1 R514.1 R515.1 R598.2 U53.1
N16860580: C473.1 C474.1 C475.1 R516.2 U53.8
N16860640: D110.2 D112.1 T1.2 U53.7
N16861242: J11.2 R517.1 T1.3
N16861249: D113.2 D114.1 T1.1 U53.6
N16861268: J11.1 R517.2 T1.4
N16861373: D111.2 D112.2 D114.2
N16866679: C488.1 R58.2 R528.1 R529.1 R600.1
N16866735: C490.1 R530.1 R531.1 R578.2 R601.1
N16867200: C492.1 R532.2 R533.1 R534.1
N16867335: R532.1 U55.2
N16868074: C264.1 R229.2 R230.2 U36.2
N16868076: R229.1 U37.1
N16868126: C265.2 R591.1 U36.5
N16868143: C266.2 R589.1 U56.8
N16868206: C495.2 R535.1 R602.2 U56.6
N16868218: C495.1 R524.1 R535.2 U37.3 U56.7
N16868269: C262.1 R226.2 R603.2 U56.5
N16868287: C267.2 R224.1 R225.2 U56.3
N16900365: Q1.1 R537.1 R538.2
N16900541: C505.1 Q1.3 R536.1 U57.7
N16908509: R540.2 R541.2 U57.19
N16911091: C263.2 R590.2 U37.5
N16917336: C483.1 R524.2 R525.1
N16935004: R547.2 U57.8
N16936023: C518.1 R544.1 R545.2 U28.59 ZD3.2
N17022031: C560.1 C561.1 C562.1 R549.1 U58.14
N17025421: C563.1 C564.1 C565.1 R550.1 U59.14
N17045637: R499.2 U60.2
N17046827: R510.1 U48.7
N17096901: C237.2 R133.1 R488.1 R573.2
N17102058: C594.1 R495.1 R506.1 R574.2 R575.1
N17145225: C595.1 R599.2 U28.56
N17156215: R579.1 R601.2
N17156241: R49.1 R600.2
N17158559: R16.2 R603.1
N17158583: R572.2 R602.1
N16779431153: R400.1 U28.154

Pads without a net: J2 1 6 8 13; J4 9 12; NOREF#3 1; NOREF#9 1; NOREF#10 1; NOREF#11 1; NOREF#12 1; NOREF#13 1; U28 9 12 13 14 17 19 24 25 27 63 64 65 66 67 69 70 71 73 74 83 84 85 86 87 89 90 92 93 94 95 96 97 98 100 101 102 103 104 105 107 110 111 112 113 115 118 122 128 129 130 131 133 134 135 136 141 142 145 146 148 149 150 151 155 156 157 161 163 165 167 170 171 172; U36 1; U57 4 5 17 18 20

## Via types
v1: diameter 0.61, hole 0.305, TOP to BOTTOM, 498 vias

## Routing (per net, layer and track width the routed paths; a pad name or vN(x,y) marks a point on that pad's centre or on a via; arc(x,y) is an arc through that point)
AGND: length 305.5
  TOP w0.381: C540.2 v1(22.86,17.78) ; D48.1 46.35,15.49 v1(46.11,15.24)
  TOP w0.508: C447.1 75.44,23.37 v1(74.93,22.86) ; v1(35.18,11.43) 34.92,11.68 C545.1 ; v1(57.76,25.43) 57.73,25.4 U55.3 ; v1(22.84,29.62) 23.07,29.84 C535.2 C534.2 C533.2 C532.2 22.99,33.66 v1(22.86,33.78) ; C472.2 v1(79.38,12.7) ; v1(51.94,30.48) C553.1 C554.1 ; C392.2 48.03,36.83 47.44,36.24 47.44,35.21 v1(48.27,34.38) 48.35,34.29 R424.1 ; v1(43.81,40.64) 44.32,40.13 C523.1 ; R416.1 R422.1 R415.1 R414.1 R425.1 57.14,34.29 v1(57.51,33.91) ; R416.1 C494.2 ; R416.1 56.13,29.08 v1(57.4,29.08) ; C505.2 6.23,27.46 v1(6.24,27.44) ; C528.1 v1(33.66,40.64) ; C536.2 v1(22.86,28.57) ; C541.1 28.09,12.42 28.09,11.91 v1(28.57,11.43) 28.7,11.43 C542.1 ; v1(53.09,10.16) 53.09,9.27 R434.2 ; C559.1 C558.1 51.69,21.59 v1(52.07,21.21) ; v1(34.1,11.42) 33.66,11.87 C544.1 ; v1(63.75,15.88) 64.14,15.49 R230.1 ; R418.1 v1(41.27,40.64) ; C543.1 32.38,12.03 v1(33,11.42) ; C546.1 v1(36.83,11.43) ; R423.1 56.73,36.83 v1(57.49,36.07) ; C393.2 50.8,6.35 v1(51.05,6.1) ; C527.1 v1(34.92,40.64) ; v1(45.09,40.64) 45.59,40.13 C522.1 R420.1 ; R421.1 42.8,40.39 v1(42.55,40.64) ; v1(42.55,10.16) 42.04,9.65 42.04,9.14 C490.2 ; R582.1 R581.1 R580.1 v1(47.37,43.05) 47.38,43.06 R588.2 ; v1(6.38,36.45) 6.04,36.11 Q1.2 ; C539.2 v1(22.86,20.32) ; C520.2 51.25,35.56 51.89,36.2 v1(52.07,36.2) ; v1(71.12,24.64) 69.98,23.5 C564.2 ; C492.2 R533.2 57.49,22.98 v1(57.65,23.15) ; C531.2 v1(22.86,34.92) ; C264.2 62.87,15.75 v1(62.74,15.88) ; C266.1 72.39,10.92 71.37,9.91 ; C530.1 v1(28.57,40.64) ; C406.1 v1(20.95,13.97) ; C550.1 v1(43.81,11.43) ; v1(52.2,10.16) 52.07,10.03 C395.2 ; C547.1 v1(39.37,11.43) ; v1(43.81,10.16) 43.94,10.16 44.45,9.65 R578.1 R530.2 ; C519.2 v1(19.06,32.38) ; C555.1 v1(51.94,27.94) ; C493.2 v1(57.15,18.41) ; C552.2 v1(51.94,31.75) ; v1(71.12,26.67) 70.69,26.67 70.05,26.04 C563.2 ; C557.1 51.05,22.73 51.62,22.73 v1(52.07,22.28) ; C551.1 v1(42.55,11.43) ; C452.2 R528.2 C488.2 R58.1 51.44,15.37 v1(51.69,15.62) ; C394.2 58.42,6.47 v1(58.73,6.16) ; C525.1 v1(38.73,40.64) ; v1(8.92,36.45) 9.53,35.84 R538.1 ; C471.2 v1(79.38,13.97) ; C565.2 69.98,24.77 70.87,25.65 v1(71.12,25.65) ; C491.2 48.14,7.5 v1(48.26,7.62) ; R448.2 v1(19.68,13.97) ; C562.2 v1(70.48,36.83) ; C378.2 v1(27.3,10.16) ; C560.2 v1(70.48,38.1) ; v1(50.16,1.4) 50.04,1.4 49.15,2.28 C592.2 ; C524.1 v1(40.01,40.64) ; v1(61.09,19.68) 59.59,19.68 ; v1(22.86,22.86) 22.86,23.01 23.35,23.5 C538.2 ; v1(52.07,19.05) C521.2 ; C596.2 v1(20.95,41.15) ; R417.1 v1(51.98,25.4) ; C549.1 v1(45.09,11.43) ; C548.1 40.64,11.56 v1(40.51,11.43) ; C409.2 v1(18.41,13.97) ; C556.1 v1(51.94,26.67) ; C529.1 v1(29.84,40.64) ; R419.1 v1(38.36,45.21) ; R410.1 v1(28.57,10.16) ; U58.7 v1(60.96,30.48) ; C526.1 v1(36.2,40.64) ; C537.2 v1(22.86,27.3) ; C561.2 v1(70.47,34.29)
  ART02 w0.127: J5.6 32.97,4.45 ; J5.6 31.75,5.67 ; J5.6 30.53,4.45 ; J5.6 31.75,3.23 ; 29.21,3.23 J5.4 ; J5.4 30.43,4.45 ; J5.4 29.21,5.67 ; J5.4 27.99,4.45 ; 63.72,45.72 J3.8 ; J3.8 64.77,44.67 ; J3.8 64.77,46.77 ; J3.8 65.82,45.72 ; J2.3 33.02,46.77 ; J2.3 31.97,45.72 ; J2.3 33.02,44.67 ; J2.3 34.07,45.72 ; J5.12 40.59,4.45 ; J5.12 39.37,5.67 ; J5.12 38.15,4.45 ; J5.12 39.37,3.23 ; 31.97,43.18 J2.4 ; J2.4 33.02,44.23 ; J2.4 34.07,43.18 ; J2.4 33.02,42.13 ; 34.51,43.18 J2.2 ; J2.2 35.56,42.13 ; J2.2 36.61,43.18 ; J2.2 35.56,44.23 ; J2.21 11.21,45.72 ; J2.21 9.11,45.72 ; J2.21 10.16,44.67 ; J2.21 10.16,46.77 ; 34.29,3.23 J5.8 ; J5.8 34.29,5.67 ; J5.8 35.51,4.45 ; J5.8 33.07,4.45 ; 62.23,44.67 J3.6 ; J3.6 63.28,45.72 ; J3.6 61.18,45.72 ; J3.6 62.23,46.77 ; J5.10 36.83,5.67 ; J5.10 36.83,3.23 ; J5.10 35.61,4.45 ; J5.10 38.05,4.45
  BOTTOM w0.152: v1(63.75,15.88) 63.8,15.82
  BOTTOM w0.254: U28.51 45.22,11.56 v1(45.09,11.43) ; U28.42 51.28,16.28 51.69,15.88 v1(51.69,15.62) 51.31,15.62 51.14,15.79 U28.43 ; U28.50 45.71,14.85 v1(46.11,15.24) ; U28.32 51.99,21.28 v1(52.07,21.21) 51.18,20.32 51.18,20.28 U28.34 ; v1(48.26,21.21) 48.26,21.06 48.54,20.79 U28.33 ; v1(41.91,15.24) 42.22,14.93 U28.57 ; U28.60 40.71,12.4 40.51,12.2 v1(40.51,11.43) ; U28.47 47.22,12.22 v1(48.82,10.62) ; U28.30 v1(52.07,22.28) ; U28.52 44.71,12.33 v1(43.81,11.43)
  BOTTOM w0.381: R484.1 73.91,26.16 74.42,26.16 v1(74.93,26.67) ; v1(10.41,27.44) 9.88,27.97 U57.9 ; v1(7.42,27.45) 7.93,27.96 U57.6 ; U37.2 66.04,14.35 65.79,14.1 64.9,14.1 64.26,14.73 R230.1 ; U36.3 v1(64.78,9.54)
  BOTTOM w0.457: v1(74.93,22.86) 75.56,22.23 U43.5
  BOTTOM w0.508: D90.1 v1(52.38,6.1) ; D88.1 57.39,26.05 v1(57.76,26.41) ; C405.2 v1(78.11,1.27) ; U32.2 v1(66.67,28.96) ; v1(57.78,31.75) 57.47,32.06 D86.1 ; D93.1 57.37,22.87 v1(57.65,23.15) ; v1(55.5,6.1) 55.56,6.16 D89.1 ; 76.89,33.66 v1(74.93,33.66) ; v1(49.15,6.1) 49.21,6.16 D91.1 ; U56.4 v1(68.58,9.53) ; C595.2 v1(45.72,6.35) ; U53.4 v1(79.38,19.05) ; C518.2 38.1,7.5 37.93,7.32 ZD3.1 v1(37.47,6.35) ; R444.2 46.69,43.69 v1(47.31,44.31) D98.1 ; C463.2 v1(75.56,34.8) ; v1(67.44,6.86) R224.2 C267.1 ; U45.5 64.14,25.3 65.82,23.62 v1(66.67,23.62) 66.92,23.37 C451.2 C450.2 ; v1(57.53,39.4) 57.53,39.82 57.03,40.32 D95.1 ; v1(61.09,19.68) C410.2 ; C484.2 57.02,28.7 v1(57.4,29.08) ; R230.1 64.14,15.49 63.8,15.82 ; C464.2 v1(71.12,31.75) ; C408.2 58.07,13.46 v1(57.56,13.97) 57.24,13.65 D92.1 ; R443.2 38.43,43.69 v1(38.43,43.69) ; D87.1 v1(58.73,6.16) ; R445.2 v1(50.8,42.55) ; D96.1 13.92,37.91 v1(13.79,37.79) ; D84.1 v1(61.91,16.82) ; v1(57.49,36.07) 57.3,35.87 D94.1 ; R446.2 v1(76.83,1.27) ; C396.2 68.07,31.63 v1(67.94,31.75) v1(67.94,28.96) ; v1(57.66,16.72) 57.55,16.82 D85.1 ; C371.1 v1(19.05,34.41) ; C448.1 R484.1 ; v1(20.95,37.59) 20.63,37.91 D97.1 ; C483.2 63.38,16.25 v1(63.75,15.88) ; v1(64.14,28.96) U32.4 ; C593.2 v1(42.55,6.35) ; C407.2 v1(75.56,1.27) ; R545.1 v1(36.2,6.35) ; U61.3 v1(75.03,28.57) ; v1(57.15,18.41) 57.02,18.29 C489.2 ; C268.1 v1(66.67,7.49) ; C265.1 62.36,10.28 63.11,9.54 v1(64.78,9.54) ; v1(19.05,29.72) C254.1 ; U32.3 v1(65.41,28.96)
  vias: v1(2.54,11.43) v1(2.54,10.16) v1(2.54,8.89) v1(3.81,11.43) v1(3.81,10.16) v1(3.81,8.89) v1(4.45,27.3) v1(4.45,26.04) v1(4.45,24.77) v1(5.08,37.47) v1(5.11,36.45) v1(5.71,26.04) v1(6.35,37.47) v1(7.62,37.47) v1(7.65,36.45) v1(8.89,37.47) v1(10.19,36.45) v1(11.46,36.45) v1(12.06,27.3) v1(12.06,26.04) v1(12.06,24.77) v1(12.45,5.46) v1(12.45,4.19) v1(13.72,5.46) v1(13.72,4.19) v1(14.61,34.92) v1(14.61,33.02) v1(14.61,31.11) v1(14.61,29.21) v1(14.61,14.61) v1(14.61,12.06) v1(14.61,9.53) v1(14.61,6.99) v1(14.99,5.46) v1(14.99,4.19) v1(15.24,36.2) v1(15.24,27.3) v1(16.51,36.83) v1(16.51,26.67) v1(17.78,36.2) v1(17.78,27.3) v1(33.15,30.48) v1(33.15,29.21) v1(33.15,27.94) v1(33.15,26.67) v1(33.15,25.4) v1(33.15,24.13) v1(33.15,22.86) v1(34.29,30.48) v1(34.29,29.21) v1(34.29,27.94) v1(34.29,26.67) v1(34.29,25.4) v1(34.29,24.13) v1(34.29,22.86) v1(35.56,30.48) v1(35.56,29.21) v1(35.56,27.94) v1(35.56,26.67) v1(35.56,25.4) v1(35.56,24.13) v1(35.56,22.86) v1(36.83,30.48) v1(36.83,29.21) v1(36.83,27.94) v1(36.83,26.67) v1(36.83,25.4) v1(36.83,24.13) v1(36.83,22.86) v1(38.1,30.48) v1(38.1,29.21) v1(38.1,27.94) v1(38.1,26.67) v1(38.1,25.4) v1(38.1,24.13) v1(38.1,22.86) v1(39.37,30.48) v1(39.37,29.21) v1(39.37,27.94) v1(39.37,26.67) v1(39.37,25.4) v1(39.37,24.13) v1(39.37,22.86) v1(40.64,30.48) v1(40.64,29.21) v1(40.64,27.94) v1(40.64,26.67) v1(40.64,25.4) v1(40.64,24.13) v1(40.64,22.86) v1(41.78,30.48) v1(41.78,29.21) v1(41.78,27.94) v1(41.78,26.67) v1(41.78,25.4) v1(41.78,24.13) v1(41.78,22.86) v1(46.99,1.27) v1(51.44,1.4) v1(52.7,1.4) v1(59.69,1.4) v1(60.96,1.4) v1(66.04,1.27) v1(67.31,1.27) v1(68.58,1.27) v1(69.85,1.27)
DGND: length 37.6
  TOP w0.381: C459.2 R497.2 v1(92.59,39.12) ; R489.1 v1(98.93,26.04) ; C453.1 v1(98.93,27.3) ; C467.2 v1(98.93,29.84) ; R508.2 v1(98.93,28.57)
  TOP w0.508: C237.1 R133.2 89.41,25.91 v1(88.9,25.4) ; R494.1 92.97,23.12 v1(92.71,22.86) ; v1(92.45,30.77) 92.5,30.72 92.5,30.51 93.16,29.84 C465.2 ; C458.2 v1(98.42,36.83)
  BOTTOM w0.381: v1(92.71,22.86) 92.84,22.73 v1(96.9,22.73) 97.54,23.37 97.54,25.14 97.79,25.4 U44.4 ; v1(97.03,34.29) 97.16,34.42 U48.4 ; 87.29,23.5 v1(88.9,23.5) ; C445.1 92.35,27.3 92.58,27.53 v1(92.58,27.94) ; C457.2 v1(88.9,22.23) U43.4
  BOTTOM w0.508: C462.2 C566.2 91.6,31.62 v1(92.45,30.77) ; C446.2 91.95,23.5 92.58,22.86 v1(92.71,22.86) ; v1(98.3,22.65) 97.79,22.14 U44.5 ; 97.16,40.89 R575.2 97.92,40.13 ; 95.89,40.96 C594.2 95.11,40.13
VDD: length 32
  TOP w0.508: v1(45.34,36.83) 45.59,37.08 C522.2 ; C543.2 v1(32.38,15.24) ; v1(48.26,26.67) C556.2 ; C530.2 28.57,36.96 v1(28.45,36.83) ; C525.2 v1(38.73,36.83) ; C535.1 v1(26.67,29.84) ; C554.2 v1(48.26,29.21) ; C526.2 v1(36.2,36.83) ; C532.1 26.39,33.66 v1(26.67,33.93) ; C548.2 v1(40.64,15.24)
  BOTTOM w0.254: v1(48.26,26.67) 48.38,26.79 U28.21 ; U28.76 32.71,14.91 v1(32.38,15.24) ; U28.137 28.71,37.1 v1(28.45,36.83) ; U28.61 40.22,14.82 v1(40.64,15.24) ; U28.117 26.11,29.28 v1(26.67,29.84) ; v1(26.67,33.93) 26.52,33.79 U28.126 ; v1(45.34,36.83) 44.71,37.45 U28.169 ; v1(36.2,36.83) 36.71,37.35 U28.153 ; v1(38.73,36.83) 39.22,37.31 U28.158 ; v1(48.26,29.21) 48.33,29.28 U28.16
  vias: v1(8.13,5.46) v1(8.13,4.19) v1(9.4,5.46) v1(9.4,4.19) v1(10.67,5.46) v1(10.67,4.19)
/TRST_P: length 13.8
  TOP w0.152: v1(28.57,6.35) R410.2 C378.1 27.3,6.35 26.67,5.71 J5.2
  BOTTOM w0.152: U28.79 31.22,11.14 30.54,10.47 30.54,8.31 v1(28.57,6.35)
/WP_PFC: length 26.2
  ART03 w0.127: v1(47.88,40.68) 47.96,40.6 61.01,40.6 62.62,38.99 65.86,38.99 v1(66.37,39.5)
  BOTTOM w0.152: v1(66.37,39.5) 66.37,38.28 66.67,37.98 R439.1 67.31,37.36 66.67,36.73 U32.7 ; U28.175 47.71,39.88 47.88,40.04 v1(47.88,40.68)
_AD_DC_CUR: length 14
  TOP w0.152: v1(50.8,10.29) C393.1 R432.1
  BOTTOM w0.152: D90.3 51.44,10 51.15,10.29 v1(50.8,10.29) 50.29,9.78 48.94,9.78 46.71,12 U28.48 46.71,14.25 46.86,14.4 48.09,14.4 48.22,14.28 U28.45
_AD_DCTEMP: length 13.8
  BOTTOM w0.152: R447.2 C408.1 58.04,12.7 D92.3 53.75,12.7 53.28,13.17 53.28,15.56 51.55,17.28 U28.40
_AD_PFCTEMP: length 14.2
  BOTTOM w0.152: U28.38 53.11,18.28 55.52,15.88 D84.3 59.05,15.88 59.31,16.13 59.31,16.89 58.3,17.9 R449.2 C410.1
_AD_VAC: length 10.1
  BOTTOM w0.152: U28.29 51.85,22.79 51.86,22.79 52.26,22.79 53.21,23.75 53.21,24.79 53.52,25.1 D88.3 54.53,25.1 54.97,25.53 54.97,26.19 54.49,26.67 R525.2 C484.1 54.49,28.83
_AD_VPFC_CTRL: length 8.6
  BOTTOM w0.152: C489.1 R529.2 54.49,20.83 54.99,21.34 54.99,21.67 54.74,21.92 D93.3 54.09,21.78 51.86,21.78 51.85,21.79 U28.31
_AD_VPFC_PROTECT: length 16.2
  TOP w0.152: v1(45.09,10.16) 45.72,9.53 R531.2 C491.1
  BOTTOM w0.152: D91.3 48.26,9.78 47.88,10.16 v1(45.09,10.16) 45.09,10.54 45.72,11.18 45.72,11.94 46.22,12.43 U28.49 46.22,14.42 48.58,16.79 U28.41
_DCOCP: length 9.4
  TOP w0.152: v1(52.1,37.25) 51.68,36.83 C392.1 R431.1
  BOTTOM w0.152: D95.3 54.64,39.37 54.81,39.19 54.81,38.76 53.44,37.39 52.24,37.39 v1(52.1,37.25) 51.14,36.28 U28.2
_PFC_OCP: length 40.9
  TOP w0.152: C596.1 R605.1 18.79,38.61 v1(18.67,38.73)
  ART03 w0.127: v1(48.26,33.02) 47.24,33.02 46.35,33.91 34.16,33.91 31.88,36.2 31.88,37.72 30.48,39.12 28.96,39.12 27.43,40.64 v1(27.58,40.64)
  BOTTOM w0.152: U28.7 49.03,33.79 v1(48.26,33.02) ; v1(27.58,40.64) 18.54,40.64 18.16,40.26 18.16,39.24 v1(18.67,38.73)
_PFCCURBSAMP: length 13.2
  TOP w0.152: C394.1 R436.2 57.15,10.03 v1(57.28,10.16)
  BOTTOM w0.152: U28.44 50.68,15.28 52.02,13.94 52.02,13.39 54.51,10.9 56.54,10.9 v1(57.28,10.16) 57.78,9.65 D87.3
AC_L_SAMP_D: length 3.3
  TOP w0.152: R16.1 25.96,42.62 J2.10
AC_N_D: length 3
  TOP w0.152: R572.1 J2.12
AD_AIR_TEMP: length 8.7
  TOP w0.152: v1(52.7,17.65) 52.7,17.77 53.34,18.41 C493.1 R534.2
  BOTTOM w0.152: U28.39 52.57,17.79 v1(52.7,17.65) 53.47,16.89 53.47,16.26 53.85,15.88 D85.3
AD_DC_CUR: length 72.8
  TOP w0.152: v1(49.78,10.29) 49.38,10.29 48.8,9.71 48.8,7.72 49.02,7.5 R432.2
  ART03 w0.127: v1(49.78,10.29) 48.13,8.64 25.02,8.64 21.34,12.32 17.66,12.32 13.47,16.51 13.47,36.71 17.78,41.02 J2.16
AD_DCVOLT1: length 13.6
  TOP w0.152: v1(53.98,10.16) 53.98,11.31 C452.1 R487.2
  BOTTOM w0.152: D89.3 54.61,9.78 54.23,10.16 v1(53.98,10.16) 51.99,12.14 48.08,12.14 47.71,12.51 U28.46
CAN5V_GND: length 47.3
  TOP w0.381: v1(96.79,14.35) 95.5,14.35 95.29,14.57 D111.1 95.29,15.49 96.11,16.31 v1(96.76,16.31)
  TOP w0.508: C474.2 v1(88.9,9.53) ; D110.1 88.88,13.42 89.17,13.13 90.77,13.13 v1(91.42,12.48) 91.44,12.51 ; C475.2 v1(87.63,9.53) ; C473.2 v1(86.36,9.53) ; 88.88,19.03 v1(88.9,19.05)
  ART03 w0.508: J4.2 92.72,44.44 88.23,44.44 87.62,43.83 87.62,41.79 86.23,40.41 86.23,21.34 88.52,19.05 v1(88.9,19.05)
  BOTTOM w0.508: U53.5 v1(88.9,19.05)
CAN_5V: length 38.6
  TOP w0.508: v1(91.44,10.54) 91.31,10.67 90.17,10.67 R516.1
  ART03 w0.508: J4.4 87.21,38.95 87.21,21.63 88.95,19.89 89.2,19.89 89.92,19.16 89.92,19.14 92.46,16.61 92.46,11.37 91.63,10.54 v1(91.44,10.54)
CANRX: length 64.3
  ART03 w0.127: v1(73.66,16.51) 73.53,16.38 66.05,16.38 63.91,18.52 61.82,18.52 61.28,19.06 60.7,19.06 58.04,21.72 46.94,21.72 44.29,19.06 29.27,19.06 24.2,24.13 v1(22.86,24.13)
  BOTTOM w0.152: U28.108 23.52,24.79 v1(22.86,24.13) R514.2 ; v1(73.66,16.51) 73.66,16.26 75.95,13.97 U53.2
CANTX: length 84.7
  ART03 w0.127: v1(29.21,34.92) 29.21,27.89 27.21,25.89 23.35,25.89 v1(22.86,25.4) 23.58,24.68 24.45,24.68 29.54,19.58 43.84,19.58 47.24,22.99 55.19,22.99 56.16,22.02 58.5,22.02 60.3,20.22 63.17,20.22 66.58,16.81 72.69,16.81 v1(73.66,17.78)
  BOTTOM w0.152: U53.3 74.94,16.51 73.66,17.79 v1(73.66,17.78) ; U28.109 22.98,25.28 v1(22.86,25.4) R515.2 ; U28.140 30.22,37.85 30.6,37.47 30.88,37.47 31.26,37.09 31.26,36.34 29.84,34.92 v1(29.21,34.92)
CS: length 105.4
  TOP w0.152: J3.1 58.43,44.46 70.29,44.46 73.36,41.39 73.36,38.04 77.47,33.93 77.47,18.41 v1(76.83,17.78)
  TOP w0.508: J3.1 54.1,46.23 46.35,46.23 R580.2 R581.2 R582.2
  ART03 w0.127: v1(76.83,17.78) 76.83,12.57 74.68,10.41 62.43,10.41 60.75,8.73 51.95,8.73 50.3,7.09 47.45,7.09 46.94,7.59 42.52,7.59 v1(41.27,6.35)
  BOTTOM w0.381: R583.1 v1(41.27,6.35)
CS_ADC: length 13.5
  TOP w0.381: v1(41.27,10.16) 41.91,10.79 46.85,10.79 D48.2
  BOTTOM w0.152: U28.58 41.71,10.6 v1(41.27,10.16) R583.2 C593.1 R599.1
CS_RTN: length 13.6
  TOP w0.508: J3.3 58.42,41.91 56.39,41.91 53.09,45.21 48.9,45.21 R588.1
DCOCP: length 56.2
  TOP w0.152: J2.18 R604.2 ; v1(52.07,39.37) 49.93,39.37 49.41,38.84 R431.2
  BOTTOM w0.152: v1(52.07,39.37) 52.3,39.37 55.04,42.11 55.04,45.53 53.54,47.03 39.24,47.03 36.64,44.43 17.21,44.43 15.96,43.18 J2.18
DCOVP: length 39.2
  ART03 w0.127: v1(47.88,41.78) 48.51,41.78 49.02,41.27 61.87,41.27 63.11,40.03 67.92,40.03 v1(68.45,39.5)
  BOTTOM w0.152: D98.3 48.26,42.16 v1(47.88,41.78) 48.64,41.02 48.64,39.75 48.22,39.33 U28.176 ; U60.4 74.42,36.2 C463.1 R502.2 70.23,36.32 69.98,36.58 69.98,40.01 69.85,40.14 69.09,40.14 v1(68.45,39.5)
DCPWM1A_1H: length 18.9
  TOP w0.152: U58.6 61.34,31.75 61.72,32.13 61.72,33.91 62.1,34.29 v1(62.23,34.29)
  BOTTOM w0.152: J3.4 58.42,44.45 58.42,42.04 59.82,40.64 59.82,35.84 60.73,34.92 61.59,34.92 v1(62.23,34.29)
DCPWM1A_1HH: length 32.6
  TOP w0.152: R419.2 39.37,42.54 v1(40.13,41.78) ; U58.5 v1(60.96,33.02)
  ART03 w0.127: v1(40.13,41.78) 40.64,41.27 40.64,40.39 43.56,37.47 48.64,37.47 51.56,34.54 58.51,34.54 60.03,33.02 v1(60.96,33.02)
  BOTTOM w0.152: v1(40.13,41.78) 40.13,41.91 39.47,41.25 39.47,40.32 40.22,39.58 U28.160
DCPWM1A_1L: length 16.5
  TOP w0.152: v1(60.96,34.04) 60.96,34.08 60.75,34.29 U58.4
  BOTTOM w0.152: v1(60.96,34.04) 59.22,35.77 59.22,39.84 57.28,41.78 56.52,41.78 55.75,42.55 55.75,44.32 J3.2
DCPWM1A_1LL: length 32.6
  TOP w0.152: R418.2 41.79,37.98 42.04,38.23 42.04,41.19 v1(41.48,41.74) ; U58.3 v1(60.96,35.56)
  ART03 w0.127: v1(41.48,41.74) 42.01,41.22 42.01,40.29 44.2,38.1 50.12,38.1 51.49,36.72 59.8,36.72 v1(60.96,35.56)
  BOTTOM w0.152: v1(41.48,41.74) 41.48,41.87 40.64,41.03 40.64,40.23 41.22,39.65 U28.162
DCPWM2A_2H: length 12.4
  TOP w0.152: U58.12 v1(62.23,35.56)
  BOTTOM w0.152: J3.7 64.11,43.18 61.58,40.65 61.58,36.21 v1(62.23,35.56)
DCPWM2A_2HH: length 37
  TOP w0.152: v1(62.23,36.83) 62.78,36.28 63.84,36.28 64.4,36.83 U58.13 ; v1(45.09,41.78) 45.72,41.15 47.12,41.15 47.37,40.89 47.37,40.3 47.49,40.18 47.5,40.18 47.68,40 47.68,40 48.01,39.67 48.01,38.48 47.5,37.98 R420.2
  ART03 w0.127: v1(45.09,41.78) 45.68,41.18 45.68,40.55 46.61,39.62 49.28,39.62 49.6,39.95 60.05,39.95 62.23,37.76 v1(62.23,36.83)
  BOTTOM w0.152: v1(45.09,41.78) 44.45,42.42 42.55,42.42 41.99,41.86 41.99,39.85 42.22,39.62 U28.164
DCPWM2A_2L: length 8.9
  TOP w0.152: U58.2 v1(60.96,36.83)
  BOTTOM w0.152: v1(60.96,36.83) 60.38,37.41 60.38,40.31 62.23,42.16 J3.5
DCPWM2A_2LL: length 29.8
  TOP w0.152: U58.1 v1(60.96,38.1) ; v1(42.55,41.66) 42.67,41.66 43.26,41.07 43.26,40.44 43.56,40.13 43.56,38.1 43.43,37.98 R421.2
  ART03 w0.127: v1(42.55,41.66) 43.18,41.02 43.18,40.51 44.96,38.73 60.33,38.73 v1(60.96,38.1)
  BOTTOM w0.152: v1(42.55,41.66) 43.22,40.99 U28.166
DCSHORT: length 37.2
  ART03 w0.127: v1(53.09,35.18) 53.16,35.11 59.57,35.11 59.75,34.92 64.9,34.92 v1(69.47,39.5)
  BOTTOM w0.152: U28.5 51.38,34.79 51.61,34.55 52.46,34.55 v1(53.09,35.18) 53.34,34.92 D94.3 ; U61.4 74.42,31.11 C464.1 R505.2 73.78,33.66 73.53,33.91 71.7,33.91 70.71,34.9 70.26,34.9 69.47,35.69 v1(69.47,39.5)
DCVOLT1: length 8.4
  TOP w0.152: C455.2 R491.2 91.72,23.01 92.05,23.01 92.66,23.62 v1(92.66,24.03)
  BOTTOM w0.152: U44.1 93.98,25.97 93.62,25.61 92.49,25.61 91.64,24.77 R482.1 92.3,24.03 v1(92.66,24.03)
P_ADREF3.2V: length 45.9
  TOP w0.508: C549.2 45.09,14.86 v1(44.71,15.23) ; v1(47.12,19.05) 47.12,21.59 47.5,21.97 48.9,21.97 49.28,21.59 C558.2 ; C559.2 48.39,20.32 v1(48.26,20.19) ; C551.2 42.55,14.94 v1(42.9,15.29) ; 55.37,10.16 54.74,9.53 54.74,9.14 R433.1
  ART03 w0.508: v1(57.78,24.51) 57.56,24.51 56.46,25.6 56.46,29.16 v1(57.4,30.1)
  BOTTOM w0.254: v1(47.12,19.05) 47.68,18.49 48.59,18.49 48.88,18.79 U28.37 ; v1(42.9,15.29) 43.22,14.98 U28.55 ; U28.53 44.22,14.73 v1(44.71,15.23) ; U28.35 48.67,19.79 v1(48.26,20.19)
  BOTTOM w0.508: v1(56.77,6.1) 56.84,6.16 D87.2 ; v1(47.37,6.1) 47.31,6.16 D91.2 ; D93.2 57.55,20.97 v1(57.66,21.08) 58.34,21.76 58.34,23.96 v1(57.78,24.51) 57.42,24.15 D88.2 ; D92.2 56.7,11.75 57.44,11.01 58.33,11.01 v1(58.55,10.79) ; v1(50.16,5.08) 50.16,6.35 50.49,6.67 D90.2 ; D89.2 53.66,6.16 v1(53.72,6.1) ; v1(57.4,30.1) 57.34,30.17 D86.2 ; v1(55.24,15.11) 55.43,14.93 D85.2 ; D84.2 v1(59.3,14.93)
  vias: v1(50.16,3.81) v1(51.44,5.08)
